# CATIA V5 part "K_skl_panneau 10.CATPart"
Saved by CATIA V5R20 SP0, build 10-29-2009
Part number: skl_panneau 10
Publications: "longueur axe pivot", "liaison 3/10", "liaison 10/21", "liaison 10/17 sur 10", "liaison 10/23 sur 10", "Plan.00", "Droite.1", "Droite.2", "Droite.3", "Droite.4", "Droite.5", "Droite.6", "Droite.7"
Bounding box of the stored display mesh (mm): x -150 to 0, y -990 to -720, z 0 to 445
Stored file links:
  G:\Khaled_CFAO_2011\SIL\SIL_GR2\mdardier\Khaled\CAD_ThinkMOTION\K_skl_panneau 10.CATPart
  G:\Khaled_CFAO_2011\SIL\SIL_GR2\mdardier\Khaled\CAD_ThinkMOTION\K_skl_ass_tandem.CATProduct
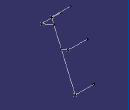
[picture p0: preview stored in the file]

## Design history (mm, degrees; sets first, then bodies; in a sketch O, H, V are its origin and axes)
External parameters (linked from other documents)
  `External.longueur axe pivot` = 150 mm
Set1
  Point1 "liaison 3/10": linked copy from another document
  Point2 "liaison 10/21": linked copy from another document
  Point3 "liaison 10/17 sur 10": linked copy from another document
  Point4 "liaison 10/23 sur 10": linked copy from another document
  Plane1 "Plan.00": linked copy from another document
Set2
  Line1: type PtPt, FirstPoint Point1, SecondPoint Point2
  Line2: type Angle, LineFirstUpto Line1, RefPoint Point3, Start 0, End 0, Angle 90
  Line3: type Angle, LineFirstUpto Line1, RefPoint Point4, Start 0, End 0, Angle -90
  Line4: type Normal, RefPoint Point1, RefSkin Plane1, Start 0, End 150 {= `External.longueur axe pivot`}
  Line5: type Normal, RefPoint Point3, RefSkin Plane1, Start 0, End 150 {= `External.longueur axe pivot`}
  Line6: type Normal, RefPoint Point4, RefSkin Plane1, Start 0, End 150 {= `External.longueur axe pivot`}
  Line7: type Normal, RefPoint Point2, RefSkin Plane1, Start 0, End 150 {= `External.longueur axe pivot`}
Body1 (main body)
